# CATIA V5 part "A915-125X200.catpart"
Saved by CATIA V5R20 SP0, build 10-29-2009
Part number: A915-125X200
Source: Unknown
Property "A": "75.000"
Property "ARTICLENO": "A915-125X200"
Property "BOMINFO": "A915-125X200"
Property "CODE": "A915-125X200"
Property "CREATOR": "CADENAS GmbH"
Property "D": "13.500"
Property "D1": "20.000"
Property "FORM": "C"
Property "L": "200.000"
Property "L1": "25.000"
Property "L2": "150.000"
Property "LINA": "A915-125X200"
Property "NB": "A915-125X200"
Property "NBSYN": "$CODE."
Property "NN": "A915"
Property "NT": "VDI 3357 Wear Plates, steel"
Property "SCREW": "M12x25"
Property "SUPPLIER": "CF"
Property "T": "13.000"
Property "W": "125.000"
Bounding box of the stored display mesh (mm): x 0 to 20, y 0 to 200, z -62.5 to 62.5
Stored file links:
  C:\Users\borellobunino\Desktop\3D X SITO CF\A915\GSB_OILLESS_G22501125200\CATIAV5\A915-125X200.catpart
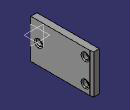
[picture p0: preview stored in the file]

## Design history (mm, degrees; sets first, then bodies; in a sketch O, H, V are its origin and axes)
Body1 "Geometry.1" (main body)
  Solid1 "A915-125X200.catpart": solid without history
